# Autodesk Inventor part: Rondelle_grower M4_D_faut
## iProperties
Created: 2011-10
Part Number: Rondelle_grower M4_D_faut
Document SubType Name: Modeling
Designer: Bruno
Author: Bruno
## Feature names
1. Base1
